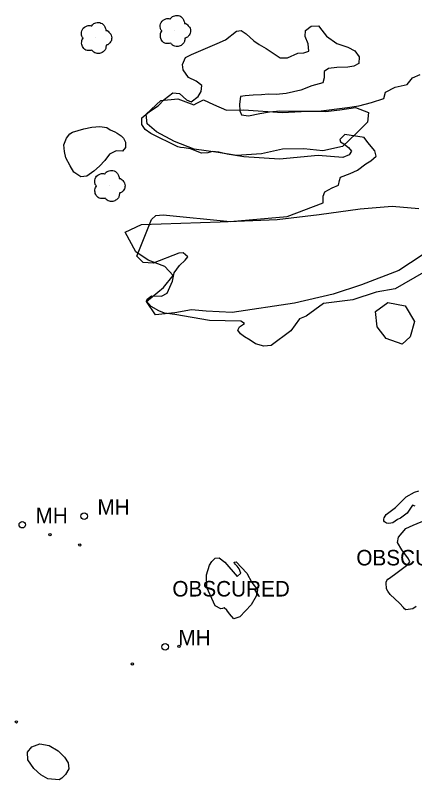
# Model space of a CAD drawing. Extents: x 368532 to 392481, y 10654822 to 10676899.
# Drawn here: x 370379.8 to 370508.6, y 10675035.1 to 10675281.6 of the extents above; entities that cross this region are included whole.
import ezdxf

# ---------------------------------------------------------------- set-up
doc = ezdxf.new("R2010")
doc.units = 0
for name, color, linetype in [('p_dtm obscured area', 7, 'Continuous'), ('p_structure unidentified', 7, 'Continuous'), ('p_utility manhole', 7, 'Continuous'), ('p_veg tree', 7, 'Continuous'), ('p_veg woods', 7, 'Continuous')]:
    doc.layers.add(name, color=color, linetype=linetype)

msp = doc.modelspace()

# ---------------------------------------------------------------- linework, layer by layer
at = {"layer": 'p_dtm obscured area'}
for points in [[(370432.25, 10675239.16), (370423.46, 10675243.4), (370421.69, 10675244.79), (370420.59, 10675246.38), (370420.59, 10675248.49), (370423.08, 10675250.58), (370425.81, 10675252.36), (370427.8, 10675254.4), (370430.6, 10675256.55), (370432.77, 10675256.36), (370434.97, 10675254.27), (370436.53, 10675253.68), (370438.73, 10675255.37), (370439.73, 10675256.96), (370439.98, 10675258.94), (370438.12, 10675260.29), (370435.69, 10675261.53), (370433.97, 10675263.95), (370433.72, 10675265.74), (370434.64, 10675267.93), (370436.63, 10675268.93), (370444.9, 10675272.47), (370447.6, 10675273.65), (370451.17, 10675276.48), (370452.68, 10675276.7), (370454.26, 10675275.58), (370456.74, 10675273.33), (370458.48, 10675272.11), (370460.69, 10675270.91), (370465.17, 10675267.81), (370467.62, 10675267.83), (370470.89, 10675269.32), (370472.9, 10675269.41), (370474.51, 10675270.04), (370474.24, 10675272.37), (370473.31, 10675274.68), (370473.43, 10675276.66), (370475.25, 10675278.04), (370477.61, 10675278.22), (370478.69, 10675276.73), (370480.16, 10675274.88), (370483.52, 10675272.43), (370487.05, 10675271.33), (370489.3, 10675270.1), (370490.71, 10675268.19), (370490.58, 10675266.02), (370489.02, 10675265.2), (370487, 10675264.85), (370483.54, 10675264.73), (370480.8, 10675264.36), (370479.46, 10675263.44), (370479.46, 10675261.4), (370478.99, 10675259.84), (370477.79, 10675259.42), (370475.39, 10675258.77), (370471.84, 10675257.38), (370467.17, 10675256.39), (370463.93, 10675256.04), (370461.48, 10675256.08), (370459.18, 10675255.96), (370456.5, 10675255.85), (370453.98, 10675255.58), (370452.47, 10675255.36), (370452.11, 10675252.91), (370452.2, 10675250.71), (370452.78, 10675249.47), (370455, 10675249.15), (370458.66, 10675249.9), (370461.82, 10675250.48), (370465.16, 10675250.74), (370477.58, 10675250.68), (370486.94, 10675251.87), (370490.63, 10675252.4), (370494.64, 10675253.43), (370498.62, 10675254.75), (370499.25, 10675256.78), (370502.3, 10675258.43), (370506.15, 10675259.24), (370507.92, 10675261.38), (370510.42, 10675262.5)], [(370511.41, 10675198.67), (370502.36, 10675193.4), (370496.23, 10675192.26), (370488.68, 10675189.77), (370479.23, 10675188.61), (370473.57, 10675184.53), (370471.45, 10675183.67), (370468.61, 10675179.79), (370462.31, 10675175.03), (370459.94, 10675174.88), (370457.26, 10675175.62), (370455.51, 10675176.79), (370453.69, 10675177.84), (370452.41, 10675178.86), (370451.6, 10675180.03), (370452.15, 10675181.05), (370453.67, 10675182.16), (370452.53, 10675182.97), (370442.37, 10675183.15), (370431.25, 10675185.04), (370427.93, 10675185.5), (370426.11, 10675186.23), (370423.59, 10675187.69), (370422.14, 10675189.33), (370422.29, 10675190.02), (370423.67, 10675191.11), (370426.9, 10675190.94), (370428.75, 10675191.98), (370430.52, 10675195.8), (370431.07, 10675198.5), (370432.71, 10675200.83), (370434.58, 10675202.65), (370435.48, 10675203.64), (370433.98, 10675204.93), (370432.52, 10675204.85), (370424.25, 10675201.64), (370421.05, 10675201.82), (370419.03, 10675203.88), (370423.76, 10675215.74), (370425.15, 10675217), (370427.46, 10675217.27), (370449.05, 10675215.06), (370467.49, 10675216.7), (370479.06, 10675221.08), (370479.04, 10675223.27), (370479.59, 10675224.59), (370482.01, 10675225.9), (370483.99, 10675226.79), (370484.35, 10675228.26), (370484.7, 10675229.36), (370487.82, 10675230.5), (370490.16, 10675231.58), (370492.82, 10675233.7), (370494.45, 10675234.66), (370496.17, 10675236.11), (370495.73, 10675237.84), (370493.54, 10675240.5), (370492.35, 10675242.15), (370486.05, 10675243.13), (370484.44, 10675241.56), (370484.64, 10675240.8), (370485.74, 10675240.08), (370487.31, 10675238.89), (370488.21, 10675237.71), (370487.44, 10675236.58), (370485.48, 10675235.75), (370477.51, 10675236.37), (370464.97, 10675235.15), (370453.54, 10675235.94), (370448.12, 10675236.76), (370445.42, 10675237.48), (370443.4, 10675237.61), (370441.84, 10675237.22), (370439.79, 10675237.14), (370436.26, 10675238.49), (370434.27, 10675238.85), (370433.02, 10675238.96), (370432.25, 10675239.16)], [(370508.74, 10675123.3), (370507.86, 10675123.6), (370506.17, 10675121.03), (370504.07, 10675119.35), (370503.12, 10675118.98), (370501.56, 10675117.91), (370500.24, 10675117.68), (370499.52, 10675117.78), (370498.85, 10675118.2), (370498.68, 10675118.53), (370498.63, 10675119.06), (370498.78, 10675119.56), (370499.43, 10675120.59), (370502.38, 10675122.84), (370505.9, 10675126.26), (370508.56, 10675127.76), (370509.96, 10675128.19)], [(370509.04, 10675090.96), (370507.98, 10675090.18), (370505.71, 10675089.85), (370505.33, 10675090.16), (370504.99, 10675090.58), (370503.72, 10675091.99), (370500.68, 10675094.78), (370499.93, 10675095.82), (370499.57, 10675096.62), (370499.49, 10675097.03), (370499.45, 10675098.15), (370499.45, 10675098.78), (370499.62, 10675099.29), (370499.97, 10675099.72), (370500.54, 10675100.08), (370502.92, 10675101.91), (370506.43, 10675104.42), (370507.03, 10675105.34), (370506.59, 10675106.31), (370504.43, 10675109.22), (370503.09, 10675111.53), (370503.37, 10675113.23), (370505.76, 10675116.07), (370508.17, 10675117.12), (370512.55, 10675118.94)]]:
    msp.add_lwpolyline(points, dxfattribs=at)
for points in [[(370398.21, 10675243.85), (370400.08, 10675244.42), (370401.88, 10675244.92), (370404.47, 10675245.51), (370407.05, 10675245.71), (370409.28, 10675245.39), (370410.4, 10675244.68), (370411.83, 10675244.03), (370412.67, 10675243.54), (370413.98, 10675242.7), (370414.69, 10675241.9), (370415.29, 10675240.63), (370415.3, 10675238.97), (370414.33, 10675237.72), (370412.29, 10675237.85), (370410.16, 10675236.73), (370408.65, 10675234.77), (370406.89, 10675232.88), (370405.16, 10675231.28), (370402.9, 10675229.71), (370400.95, 10675229.43), (370398.62, 10675231.02), (370397.46, 10675233.05), (370396.03, 10675235.62), (370395.62, 10675237.64), (370395.47, 10675239.78), (370396.32, 10675241.9), (370397.32, 10675243.3)], [(370450.98, 10675105.32), (370454.45, 10675101.7), (370456.06, 10675098.68), (370457.94, 10675096.32), (370457.47, 10675094.24), (370455.82, 10675091.47), (370452.19, 10675087.61), (370450.28, 10675086.89), (370448.89, 10675088.53), (370447.99, 10675089.69), (370447.17, 10675090.51), (370446.61, 10675090.28), (370446.13, 10675090.14), (370444.24, 10675091.12), (370441.52, 10675097.07), (370441.44, 10675101.12), (370442.43, 10675104.22), (370443.13, 10675105.39), (370444.27, 10675106.48), (370445.54, 10675106.6), (370447.39, 10675105.2), (370451.38, 10675100.64), (370452.5, 10675101.71), (370451.96, 10675103.04), (370451.37, 10675103.94), (370450.71, 10675104.59), (370450.45, 10675104.94), (370450.41, 10675105.18)]]:
    msp.add_lwpolyline(points, close=True, dxfattribs=at)
at = {"layer": 'p_structure unidentified'}
for centre in [(370390.96, 10675114.13), (370400.59, 10675110.71), (370432.54, 10675078.12), (370417.55, 10675072.39), (370380.14, 10675053.72)]:
    msp.add_circle(centre, 0.375, dxfattribs=at)
at = {"layer": 'p_utility manhole'}
for centre in [(370402.01, 10675120.04), (370382.04, 10675117.29), (370428.12, 10675077.89)]:
    msp.add_circle(centre, 1.05, dxfattribs=at)
at = {"layer": 'p_veg tree'}
for p, q in [((370431.19, 10675276.52), (370431.19, 10675276.52)), ((370405.77, 10675274.26), (370405.77, 10675274.26)), ((370410.06, 10675226.55), (370410.06, 10675226.55))]:
    msp.add_line(p, q, dxfattribs=at)
for points in [[(370429.92, 10675272.55), (370428.37, 10675272.48), (370427.04, 10675273.39), (370426.59, 10675274.83), (370426.66, 10675275.68), (370426.97, 10675276.31), (370427.07, 10675276.42), (370427.01, 10675276.51), (370426.59, 10675277.38), (370426.84, 10675279.29), (370428.37, 10675280.44), (370429.67, 10675280.42), (370429.81, 10675280.38), (370429.88, 10675280.48), (370430.81, 10675281.26), (370432.42, 10675281.47), (370433.82, 10675280.56), (370434.29, 10675279.58), (370434.38, 10675279.04), (370434.37, 10675278.92), (370434.48, 10675278.93), (370435.09, 10675278.66), (370435.97, 10675277.74), (370436.28, 10675276.19), (370435.7, 10675274.92), (370434.78, 10675274.26), (370434.53, 10675274.18), (370434.48, 10675274.13), (370434.47, 10675274.07), (370434.44, 10675273.61), (370434.15, 10675272.68), (370433.25, 10675271.87), (370432.05, 10675271.49), (370430.52, 10675271.96), (370429.9, 10675272.56)], [(370404.51, 10675270.29), (370402.96, 10675270.22), (370401.63, 10675271.13), (370401.18, 10675272.57), (370401.25, 10675273.42), (370401.56, 10675274.04), (370401.66, 10675274.16), (370401.59, 10675274.25), (370401.18, 10675275.11), (370401.43, 10675277.03), (370402.95, 10675278.18), (370404.26, 10675278.16), (370404.4, 10675278.12), (370404.47, 10675278.22), (370405.4, 10675279), (370407, 10675279.2), (370408.41, 10675278.3), (370408.88, 10675277.32), (370408.97, 10675276.77), (370408.96, 10675276.66), (370409.06, 10675276.67), (370409.68, 10675276.4), (370410.56, 10675275.47), (370410.86, 10675273.93), (370410.29, 10675272.66), (370409.37, 10675271.99), (370409.12, 10675271.92), (370409.07, 10675271.87), (370409.06, 10675271.8), (370409.03, 10675271.35), (370408.74, 10675270.42), (370407.84, 10675269.61), (370406.64, 10675269.22), (370405.11, 10675269.7), (370404.49, 10675270.3)], [(370408.8, 10675222.58), (370407.24, 10675222.51), (370405.91, 10675223.42), (370405.46, 10675224.86), (370405.53, 10675225.71), (370405.85, 10675226.34), (370405.95, 10675226.45), (370405.88, 10675226.54), (370405.46, 10675227.4), (370405.71, 10675229.32), (370407.24, 10675230.47), (370408.54, 10675230.45), (370408.69, 10675230.41), (370408.75, 10675230.51), (370409.69, 10675231.29), (370411.29, 10675231.49), (370412.7, 10675230.59), (370413.17, 10675229.61), (370413.26, 10675229.07), (370413.24, 10675228.95), (370413.35, 10675228.96), (370413.96, 10675228.69), (370414.85, 10675227.76), (370415.15, 10675226.22), (370414.58, 10675224.95), (370413.66, 10675224.29), (370413.4, 10675224.21), (370413.35, 10675224.16), (370413.35, 10675224.1), (370413.31, 10675223.64), (370413.03, 10675222.71), (370412.13, 10675221.9), (370410.93, 10675221.52), (370409.4, 10675221.99), (370408.78, 10675222.59)]]:
    msp.add_spline(points, degree=3, dxfattribs=at)
at = {"layer": 'p_veg woods'}
for points in [[(370467.88, 10675250.34), (370474.03, 10675250.69), (370479.86, 10675250.52), (370484.42, 10675251.04), (370489.47, 10675251.81), (370493.69, 10675250.23), (370493.36, 10675247.05), (370489.71, 10675243.44), (370485.31, 10675239.26), (370479.02, 10675237.89), (370472.82, 10675238.48), (370465.94, 10675238.39), (370459.19, 10675236.94), (370451.14, 10675236.36), (370445.19, 10675237.36), (370437.44, 10675238.38), (370431.12, 10675240.86), (370425.36, 10675243.97), (370422.36, 10675246.55), (370422.01, 10675249.72), (370426.73, 10675254.07), (370432.19, 10675254.64), (370437.34, 10675252.65), (370438.35, 10675253.28), (370440.45, 10675254.34), (370443.76, 10675252.79), (370447.96, 10675250.96), (370453.34, 10675251.05), (370465.95, 10675250.27)], [(370499.43, 10675177.33), (370496.53, 10675181.11), (370495.95, 10675186.03), (370499.95, 10675188.98), (370505.49, 10675187.91), (370508.56, 10675182.85), (370507.14, 10675177.86), (370504.57, 10675175.56)], [(370390.25, 10675035.37), (370387.99, 10675036.62), (370385.79, 10675038.69), (370383.83, 10675041.5), (370383.71, 10675043.96), (370385.09, 10675045.68), (370387.66, 10675046.61), (370390.69, 10675046.1), (370393.56, 10675044.36), (370395.66, 10675042.32), (370396.85, 10675040.54), (370397.01, 10675038.59), (370395.96, 10675036.79), (370394.81, 10675035.6), (370393.94, 10675035.06)]]:
    msp.add_lwpolyline(points, close=True, dxfattribs=at)
msp.add_lwpolyline([(370511.05, 10675204.24), (370503.5, 10675199.31), (370491.41, 10675194.6), (370482.37, 10675191.62), (370469.82, 10675188.68), (370449.7, 10675185.68), (370441.33, 10675186.12), (370436.61, 10675186.6), (370431.19, 10675185.58), (370425, 10675184.93), (370422.08, 10675189.24), (370427.6, 10675193.78), (370430.67, 10675197.68), (370428.03, 10675200.57), (370422.67, 10675202.62), (370418.61, 10675205.29), (370415.26, 10675211.67), (370420.46, 10675214.06), (370445.89, 10675215), (370464.26, 10675215.74), (370477.83, 10675217.35), (370491, 10675219.2), (370501.31, 10675220.01), (370509.93, 10675219.21)], dxfattribs=at)

# ---------------------------------------------------------------- texts
at = {"layer": 'p_dtm obscured area'}
for p in [(370487.93, 10675104.16), (370428.59, 10675094.14)]:
    msp.add_text(' OBSCURED', height=5, dxfattribs=at).set_placement(p)
at = {"layer": 'p_utility manhole'}
for p in [(370406.28, 10675120.5), (370386.31, 10675117.76), (370432.39, 10675078.36)]:
    msp.add_text('MH', height=5, dxfattribs=at).set_placement(p)

doc.saveas('drawing.dxf')
